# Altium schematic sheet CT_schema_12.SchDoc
size 147 x 119 mm
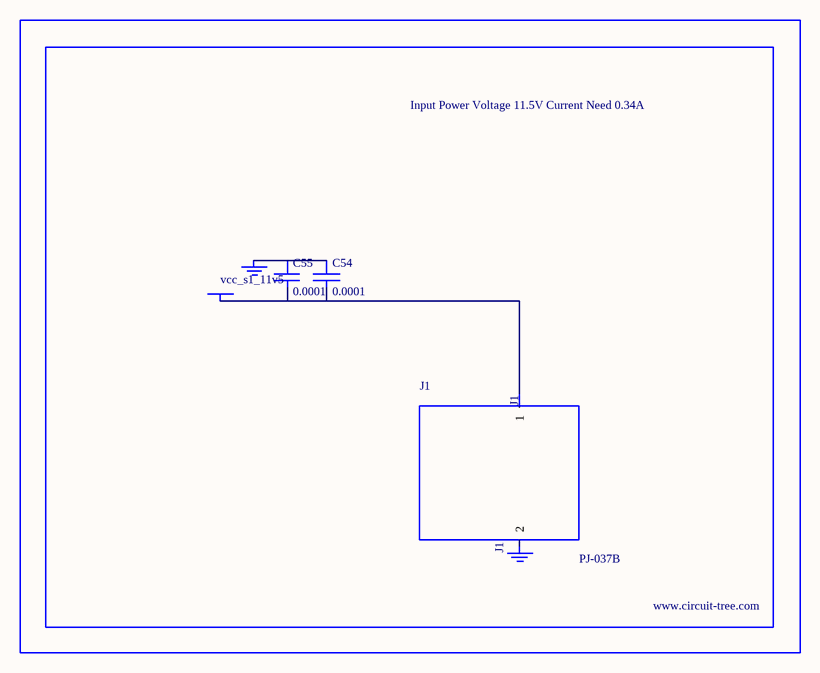
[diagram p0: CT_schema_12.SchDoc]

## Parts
BORDER11  (no value)
C54  0.0001  [EXV-9H]
C55  0.0001  [EXV-9H]
GND_INSTANCE_11_0  (no value)
GND_INSTANCE_11_1  (no value)
J1  PJ-037B  [PJ-037B_PACKAGE]
POWER_INSTANCE_11_0  vcc_s1_11v5

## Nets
NetC54_1: C54.1 C55.1 GND_INSTANCE_11_0.0(GND)
NetC54_2: C54.2 C55.2 J1.1 POWER_INSTANCE_11_0.0(PWR)

Not connected (* = marked no-connect by the designer): GND_INSTANCE_11_1 0(GND); J1 2

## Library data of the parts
BORDER11 = BORDER_PAGE11
C54 C55 = EDK107M035A9HAA
GND_INSTANCE_11_0 GND_INSTANCE_11_1 = GND
POWER_INSTANCE_11_0 = PWR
